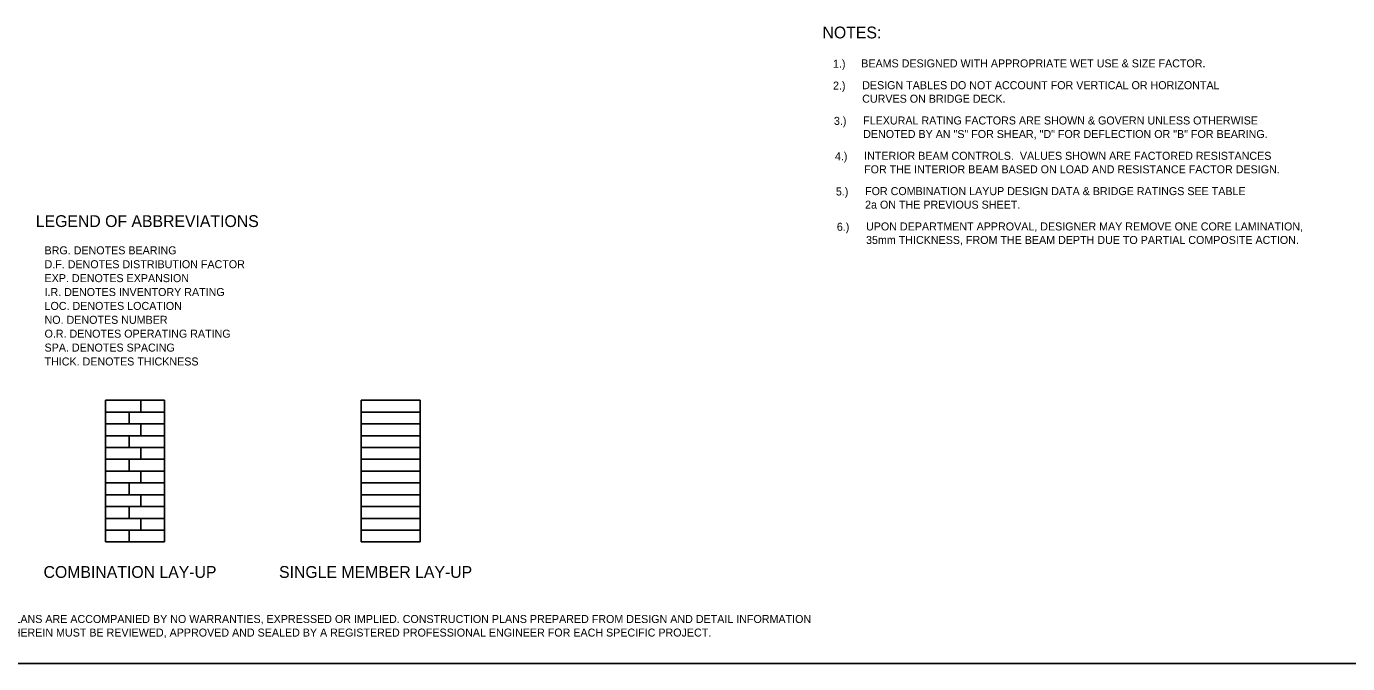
# Model space of a CAD drawing. Extents: x -5022 to -159, y 1126 to 7226.
# Drawn here: x -4608.1 to -4112.8, y 4110.8 to 4349.7 of the extents above; entities that cross this region are included whole.
import ezdxf

# ---------------------------------------------------------------- set-up
doc = ezdxf.new("R2010")
doc.units = 0
doc.layers.add('2', color=7, linetype='Continuous')

msp = doc.modelspace()

# ---------------------------------------------------------------- linework, layer by layer
at = {"layer": '2'}
for p, q in [((-4578.48, 4209.54), (-4578.48, 4156.39)), ((-4578.48, 4209.54), (-4556.33, 4209.54)), ((-4565.19, 4209.54), (-4565.19, 4205.11)), ((-4556.33, 4209.54), (-4556.33, 4156.39)), ((-4482.55, 4209.54), (-4482.55, 4156.39)), ((-4482.55, 4209.54), (-4460.4, 4209.54)), ((-4460.4, 4209.54), (-4460.4, 4156.39)), ((-4578.48, 4205.11), (-4556.33, 4205.11)), ((-4578.48, 4200.68), (-4556.33, 4200.68)), ((-4569.62, 4205.11), (-4569.62, 4200.68)), ((-4565.19, 4200.68), (-4565.19, 4196.25)), ((-4482.55, 4205.11), (-4460.4, 4205.11)), ((-4482.55, 4200.68), (-4460.4, 4200.68)), ((-4578.48, 4196.25), (-4556.33, 4196.25)), ((-4569.62, 4196.25), (-4569.62, 4191.82)), ((-4482.55, 4196.25), (-4460.4, 4196.25)), ((-4578.48, 4191.82), (-4556.33, 4191.82)), ((-4565.19, 4191.82), (-4565.19, 4187.39)), ((-4482.55, 4191.82), (-4460.4, 4191.82)), ((-4578.48, 4187.39), (-4556.33, 4187.39)), ((-4569.62, 4187.39), (-4569.62, 4182.96)), ((-4482.55, 4187.39), (-4460.4, 4187.39)), ((-4578.48, 4182.96), (-4556.33, 4182.96)), ((-4565.19, 4182.96), (-4565.19, 4178.53)), ((-4482.55, 4182.96), (-4460.4, 4182.96)), ((-4578.48, 4178.53), (-4556.33, 4178.53)), ((-4569.62, 4178.53), (-4569.62, 4174.1)), ((-4482.55, 4178.53), (-4460.4, 4178.53)), ((-4578.48, 4174.1), (-4556.33, 4174.1)), ((-4565.19, 4174.1), (-4565.19, 4169.67)), ((-4482.55, 4174.1), (-4460.4, 4174.1)), ((-4578.48, 4169.67), (-4556.33, 4169.67)), ((-4569.62, 4169.67), (-4569.62, 4165.24)), ((-4482.55, 4169.67), (-4460.4, 4169.67)), ((-4578.48, 4165.24), (-4556.33, 4165.24)), ((-4578.48, 4160.81), (-4556.33, 4160.81)), ((-4569.62, 4160.81), (-4569.62, 4156.39)), ((-4565.19, 4165.24), (-4565.19, 4160.81)), ((-4482.55, 4165.24), (-4460.4, 4165.24)), ((-4482.55, 4160.81), (-4460.4, 4160.81)), ((-4578.48, 4156.39), (-4556.33, 4156.39)), ((-4482.55, 4156.39), (-4460.4, 4156.39)), ((-3855.13, 4110.81), (-4641.13, 4110.81))]:
    msp.add_line(p, q, dxfattribs=at)

# ---------------------------------------------------------------- texts
for s, height, p in [('NOTES:', 4.429, (-4309.61, 4345.2)), ('1.)', 3, (-4305.68, 4334.2)), ('BEAMS DESIGNED WITH APPROPRIATE WET USE & SIZE FACTOR.', 3.0001, (-4295.09, 4334.33)), ('DESIGN TABLES DO NOT ACCOUNT FOR VERTICAL OR HORIZONTAL', 3.0001, (-4294.73, 4326.16)), ('2.)', 3, (-4305.68, 4326.02)), ('CURVES ON BRIDGE DECK.', 3.0001, (-4294.73, 4321.09)), ('3.)', 3, (-4305.32, 4312.78)), ('FLEXURAL RATING FACTORS ARE SHOWN & GOVERN UNLESS OTHERWISE', 3.0001, (-4294.37, 4312.93)), ('DENOTED BY AN "S" FOR SHEAR, "D" FOR DEFLECTION OR "B" FOR BEARING.', 3.0001, (-4294.37, 4307.85)), ('4.)', 3, (-4304.96, 4299.54)), ('INTERIOR BEAM CONTROLS.  VALUES SHOWN ARE FACTORED RESISTANCES', 3.0001, (-4294.01, 4299.68)), ('FOR THE INTERIOR BEAM BASED ON LOAD AND RESISTANCE FACTOR DESIGN.', 3.0001, (-4294.01, 4294.61)), ('5.)', 3, (-4304.6, 4286.3)), ('FOR COMBINATION LAYUP DESIGN DATA & BRIDGE RATINGS SEE TABLE', 3.0001, (-4293.65, 4286.44)), ('2a ON THE PREVIOUS SHEET.', 3.0001, (-4293.65, 4281.37)), ('LEGEND OF ABBREVIATIONS', 4.4293, (-4604.58, 4274.48)), ('6.)', 3, (-4304.24, 4273.06)), ('UPON DEPARTMENT APPROVAL, DESIGNER MAY REMOVE ONE CORE LAMINATION, ', 3.0001, (-4293.29, 4273.2)), ('35mm THICKNESS, FROM THE BEAM DEPTH DUE TO PARTIAL COMPOSITE ACTION.', 3.0001, (-4293.29, 4268.13)), ('BRG. DENOTES BEARING', 3.0001, (-4601.29, 4264.24)), ('D.F. DENOTES DISTRIBUTION FACTOR', 3.0001, (-4601.29, 4259.03)), ('EXP. DENOTES EXPANSION', 3.0001, (-4601.29, 4253.82)), ('I.R. DENOTES INVENTORY RATING', 3.0001, (-4601.29, 4248.61)), ('LOC. DENOTES LOCATION', 3.0001, (-4601.29, 4243.4)), ('NO. DENOTES NUMBER', 3.0001, (-4601.29, 4238.19)), ('O.R. DENOTES OPERATING RATING', 3.0001, (-4601.29, 4232.99)), ('SPA. DENOTES SPACING', 3.0001, (-4601.29, 4227.78)), ('THICK. DENOTES THICKNESS', 3.0001, (-4601.29, 4222.57)), ('COMBINATION LAY-UP', 4.4293, (-4601.66, 4142.93)), ('SINGLE MEMBER LAY-UP', 4.4293, (-4513.37, 4142.93)), ('THESE PLANS ARE ACCOMPANIED BY NO WARRANTIES, EXPRESSED OR IMPLIED. CONSTRUCTION PLANS PREPARED FROM DESIGN AND DETAIL INFORMATION', 3.00008, (-4629.74, 4126.02)), ('SHOWN HEREIN MUST BE REVIEWED, APPROVED AND SEALED BY A REGISTERED PROFESSIONAL ENGINEER FOR EACH SPECIFIC PROJECT.', 3.00008, (-4629.74, 4120.93))]:
    msp.add_text(s, height=height, dxfattribs=at).set_placement(p)

doc.saveas('drawing.dxf')
